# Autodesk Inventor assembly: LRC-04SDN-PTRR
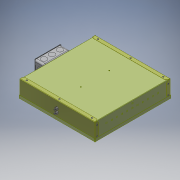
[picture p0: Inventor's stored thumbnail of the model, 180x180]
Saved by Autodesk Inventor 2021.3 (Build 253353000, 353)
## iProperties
Part Number: LRC-04SDN-PTRR
Document SubType Name: Assembly
Designer: JChurch
Author: JChurch
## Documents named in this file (6)
- X:\Revit Files\0000-Un-Zipped\COB\LRC-04SDN-PTR\LRC-04SDN-PTRR.iam
- X:\INVENTOR\830\830520-00-00.ipt
- X:\INVENTOR\885\885000-00-00.iam
- X:\INVENTOR\750\750472-00-00.iam
- X:\INVENTOR\725\725383-00-00.ipt
- X:\INVENTOR\501\501087-00-00.ipt
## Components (8 placed, 5 different names)
1. 830520-00-00:1 — Mate:1, Mate:2, Mate:3, Mate:4, Mate:5, Angle:1, Insert:2
2. 885000-00-00:1 [sub-assembly] — Mate:4, Mate:5, Angle:1
3. 750472-00-00:1 [sub-assembly] — Insert:1, Insert:2, Insert:3, Insert:4, Insert:5, Insert:6
4. 725383-00-00:1 — Insert:1
5. 501087-00-00:1 — Insert:3
6. 501087-00-00:2 — Insert:4
7. 501087-00-00:3 — Insert:5
8. 501087-00-00:4 — Insert:6
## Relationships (12: Insert 6, Mate 5, Angle 1)
- Mate:1: 830520-00-00:1
- Mate:2: 830520-00-00:1
- Mate:3: 830520-00-00:1
- Mate:4: 830520-00-00:1 ↔ 885000-00-00:1
- Mate:5: 830520-00-00:1 ↔ 885000-00-00:1
- Angle:1: 830520-00-00:1 ↔ 885000-00-00:1
- Insert:1: 750472-00-00:1 ↔ 725383-00-00:1
- Insert:2: 830520-00-00:1 ↔ 750472-00-00:1
- Insert:3: 750472-00-00:1 ↔ 501087-00-00:1
- Insert:4: 750472-00-00:1 ↔ 501087-00-00:2
- Insert:5: 750472-00-00:1 ↔ 501087-00-00:3
- Insert:6: 750472-00-00:1 ↔ 501087-00-00:4
